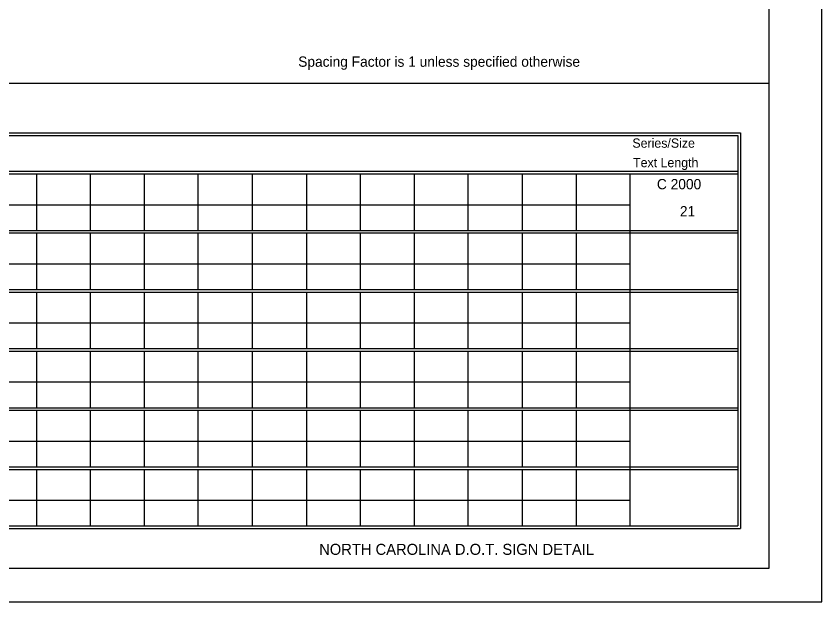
# Model space of a CAD drawing. Extents: x 57.2 to 85.4, y 153.3 to 173.4.
# Drawn here: x 78.56 to 85.38, y 163.43 to 168.39 of the extents above; entities that cross this region are included whole.
import ezdxf

# ---------------------------------------------------------------- set-up
doc = ezdxf.new("R2010")
doc.units = 0
doc.layers.add('Exist Sign D', color=7, linetype='Continuous')
doc.layers.add('Old_Level_2', color=7, linetype='Continuous')

msp = doc.modelspace()

# ---------------------------------------------------------------- linework, layer by layer
at = {"layer": 'Exist Sign D'}
msp.add_lwpolyline([(85.3839, 173.3509), (70.5057, 173.3509), (70.5057, 163.4285), (85.3839, 163.4285)], close=True, dxfattribs=at)
at = {"layer": 'Old_Level_2'}
for p, q in [((76.3534, 167.8204), (84.9353, 167.8204)), ((70.9539, 167.0753), (81.8429, 167.0753)), ((70.9539, 167.0535), (81.8429, 167.0535)), ((78.7311, 167.0535), (78.7311, 166.5748)), ((79.1855, 167.0535), (79.1855, 166.5748)), ((79.6446, 167.0535), (79.6446, 166.5748)), ((80.0991, 167.0535), (80.0991, 166.5748)), ((80.5582, 167.0535), (80.5582, 166.5748)), ((81.0174, 167.0535), (81.0174, 166.5748)), ((81.3556, 167.0753), (84.6717, 167.0753)), ((81.3556, 167.0535), (84.6717, 167.0535)), ((81.4718, 167.0535), (81.4718, 166.5748)), ((81.4718, 167.0535), (81.4718, 166.5748)), ((81.931, 167.0535), (81.931, 166.5748)), ((82.3854, 167.0535), (82.3854, 166.5748)), ((82.8445, 167.0535), (82.8445, 166.5748)), ((83.3037, 167.0535), (83.3037, 166.5748)), ((83.7581, 167.0535), (83.7581, 164.1081)), ((71.413, 166.7924), (81.8429, 166.7924)), ((81.3556, 166.7924), (83.7581, 166.7924)), ((83.7581, 166.6932), (83.7581, 166.5748)), ((70.9539, 166.5748), (81.8429, 166.5748)), ((70.9539, 166.553), (81.8429, 166.553)), ((78.7311, 166.553), (78.7311, 166.0743)), ((79.1855, 166.553), (79.1855, 166.0743)), ((79.6446, 166.553), (79.6446, 166.0743)), ((80.0991, 166.553), (80.0991, 166.0743)), ((80.5582, 166.553), (80.5582, 166.0743)), ((81.0174, 166.553), (81.0174, 166.0743)), ((81.3556, 166.5748), (84.6717, 166.5748)), ((81.3556, 166.553), (84.6717, 166.553)), ((81.4718, 166.553), (81.4718, 166.0743)), ((81.4718, 166.553), (81.4718, 166.0743)), ((81.931, 166.553), (81.931, 166.0743)), ((82.3854, 166.553), (82.3854, 166.0743)), ((82.8445, 166.553), (82.8445, 166.0743)), ((83.3037, 166.553), (83.3037, 166.0743)), ((83.7581, 166.553), (83.7581, 166.3259)), ((71.413, 166.2919), (81.8429, 166.2919)), ((81.3556, 166.2919), (83.7581, 166.2919)), ((83.7581, 166.2301), (83.7581, 166.0743)), ((70.9539, 166.0743), (81.8429, 166.0743)), ((81.3556, 166.0743), (84.6717, 166.0743)), ((70.9539, 166.0526), (81.8429, 166.0526)), ((78.7311, 166.0526), (78.7311, 165.5738)), ((79.1855, 166.0526), (79.1855, 165.5738)), ((79.6446, 166.0526), (79.6446, 165.5738)), ((80.0991, 166.0526), (80.0991, 165.5738)), ((80.5582, 166.0526), (80.5582, 165.5738)), ((81.0174, 166.0526), (81.0174, 165.5738)), ((81.3556, 166.0526), (84.6717, 166.0526)), ((81.4718, 166.0526), (81.4718, 165.5738)), ((81.4718, 166.0526), (81.4718, 165.5738)), ((81.931, 166.0526), (81.931, 165.5738)), ((82.3854, 166.0526), (82.3854, 165.5738)), ((82.8445, 166.0526), (82.8445, 165.5738)), ((83.3037, 166.0526), (83.3037, 165.5738)), ((83.7581, 166.0526), (83.7581, 165.858)), ((71.413, 165.7914), (81.8429, 165.7914)), ((81.3556, 165.7914), (83.7581, 165.7914)), ((83.7581, 165.7148), (83.7581, 165.5738)), ((70.9539, 165.5738), (81.8429, 165.5738)), ((70.9539, 165.5521), (81.8429, 165.5521)), ((78.7311, 165.5521), (78.7311, 165.0733)), ((79.1855, 165.5521), (79.1855, 165.0733)), ((79.6446, 165.5521), (79.6446, 165.0733)), ((80.0991, 165.5521), (80.0991, 165.0733)), ((80.5582, 165.5521), (80.5582, 165.0733)), ((81.0174, 165.5521), (81.0174, 165.0733)), ((81.3556, 165.5738), (84.6717, 165.5738)), ((81.3556, 165.5521), (84.6717, 165.5521)), ((81.4718, 165.5521), (81.4718, 165.0733)), ((81.4718, 165.5521), (81.4718, 165.0733)), ((81.931, 165.5521), (81.931, 165.0733)), ((82.3854, 165.5521), (82.3854, 165.0733)), ((82.8445, 165.5521), (82.8445, 165.0733)), ((83.3037, 165.5521), (83.3037, 165.0733)), ((83.7581, 165.5521), (83.7581, 165.3423)), ((71.413, 165.2909), (81.8429, 165.2909)), ((81.3556, 165.2909), (83.7581, 165.2909)), ((83.7581, 165.1991), (83.7581, 165.0733)), ((78.7311, 165.1291), (78.7311, 165.0733)), ((79.1855, 165.1291), (79.1855, 165.0733)), ((79.6446, 165.1291), (79.6446, 165.0733)), ((80.0991, 165.1291), (80.0991, 165.0733)), ((80.5582, 165.1291), (80.5582, 165.0733)), ((81.0174, 165.1291), (81.0174, 165.0733)), ((81.4718, 165.1291), (81.4718, 165.0733)), ((81.4718, 165.1291), (81.4718, 165.0733)), ((81.931, 165.1291), (81.931, 165.0733)), ((82.3854, 165.1291), (82.3854, 165.0733)), ((82.8445, 165.1291), (82.8445, 165.0733)), ((83.3037, 165.1291), (83.3037, 165.0733)), ((83.7581, 165.1291), (83.7581, 165.0733)), ((70.9539, 165.0733), (81.8429, 165.0733)), ((70.9539, 165.0733), (81.8429, 165.0733)), ((70.9539, 165.0516), (81.8429, 165.0516)), ((70.9539, 165.0516), (81.8429, 165.0516)), ((78.7311, 165.0516), (78.7311, 164.6042)), ((78.7311, 165.0516), (78.7311, 164.5729)), ((79.1855, 165.0516), (79.1855, 164.6042)), ((79.1855, 165.0516), (79.1855, 164.5729)), ((79.6446, 165.0516), (79.6446, 164.6042)), ((79.6446, 165.0516), (79.6446, 164.5729)), ((80.0991, 165.0516), (80.0991, 164.6042)), ((80.0991, 165.0516), (80.0991, 164.5729)), ((80.5582, 165.0516), (80.5582, 164.6042)), ((80.5582, 165.0516), (80.5582, 164.5729)), ((81.0174, 165.0516), (81.0174, 164.6042)), ((81.0174, 165.0516), (81.0174, 164.5729)), ((81.3556, 165.0733), (84.6717, 165.0733)), ((81.3556, 165.0733), (84.6717, 165.0733)), ((81.3556, 165.0516), (84.6717, 165.0516)), ((81.3556, 165.0516), (84.6717, 165.0516)), ((81.4718, 165.0516), (81.4718, 164.6042)), ((81.4718, 165.0516), (81.4718, 164.5729)), ((81.4718, 165.0516), (81.4718, 164.6042)), ((81.4718, 165.0516), (81.4718, 164.5729)), ((81.931, 165.0516), (81.931, 164.6042)), ((81.931, 165.0516), (81.931, 164.5729)), ((82.3854, 165.0516), (82.3854, 164.6042)), ((82.3854, 165.0516), (82.3854, 164.5729)), ((82.8445, 165.0516), (82.8445, 164.6042)), ((82.8445, 165.0516), (82.8445, 164.5729)), ((83.3037, 165.0516), (83.3037, 164.6042)), ((83.3037, 165.0516), (83.3037, 164.5729)), ((83.7581, 165.0516), (83.7581, 164.8362)), ((83.7581, 165.0516), (83.7581, 164.8362)), ((71.413, 164.7905), (81.8429, 164.7905)), ((71.413, 164.7905), (81.8429, 164.7905)), ((81.3556, 164.7905), (83.7581, 164.7905)), ((81.3556, 164.7905), (83.6391, 164.7905)), ((83.7581, 164.7121), (83.7581, 164.6042)), ((83.7581, 164.7121), (83.7581, 164.5729)), ((78.7311, 164.6286), (78.7311, 164.5729)), ((79.1855, 164.6286), (79.1855, 164.5729)), ((79.6446, 164.6286), (79.6446, 164.5729)), ((80.0991, 164.6286), (80.0991, 164.5729)), ((80.5582, 164.6286), (80.5582, 164.5729)), ((81.0174, 164.6286), (81.0174, 164.5729)), ((81.4718, 164.6286), (81.4718, 164.5729)), ((81.4718, 164.6286), (81.4718, 164.5729)), ((81.931, 164.6286), (81.931, 164.5729)), ((82.3854, 164.6286), (82.3854, 164.5729)), ((82.8445, 164.6286), (82.8445, 164.5729)), ((83.3037, 164.6286), (83.3037, 164.5729)), ((83.7581, 164.6286), (83.7581, 164.5729)), ((70.9539, 164.5729), (81.8429, 164.5729)), ((70.9539, 164.5729), (81.8429, 164.5729)), ((81.3556, 164.5729), (84.6717, 164.5729)), ((81.3556, 164.5729), (84.6717, 164.5729)), ((70.9539, 164.5511), (81.8429, 164.5511)), ((70.9539, 164.5511), (81.8429, 164.5511)), ((78.7311, 164.5511), (78.7311, 164.0724)), ((78.7311, 164.5511), (78.7311, 164.0724)), ((79.1855, 164.5511), (79.1855, 164.0724)), ((79.1855, 164.5511), (79.1855, 164.0724)), ((79.6446, 164.5511), (79.6446, 164.0724)), ((79.6446, 164.5511), (79.6446, 164.0724)), ((80.0991, 164.5511), (80.0991, 164.0724)), ((80.0991, 164.5511), (80.0991, 164.0724)), ((80.5582, 164.5511), (80.5582, 164.0724)), ((80.5582, 164.5511), (80.5582, 164.0724)), ((81.0174, 164.5511), (81.0174, 164.0724)), ((81.0174, 164.5511), (81.0174, 164.0724)), ((81.3556, 164.5511), (84.6717, 164.5511)), ((81.3556, 164.5511), (84.6717, 164.5511)), ((81.4718, 164.5511), (81.4718, 164.0724)), ((81.4718, 164.5511), (81.4718, 164.0724)), ((81.4718, 164.5511), (81.4718, 164.0724)), ((81.4718, 164.5511), (81.4718, 164.0724)), ((81.931, 164.5511), (81.931, 164.0724)), ((81.931, 164.5511), (81.931, 164.0724)), ((82.3854, 164.5511), (82.3854, 164.0724)), ((82.3854, 164.5511), (82.3854, 164.0724)), ((82.8445, 164.5511), (82.8445, 164.0724)), ((82.8445, 164.5511), (82.8445, 164.0724)), ((83.3037, 164.5511), (83.3037, 164.0724)), ((83.3037, 164.5511), (83.3037, 164.0724)), ((83.7581, 164.5511), (83.7581, 164.3496)), ((83.7581, 164.5511), (83.7581, 164.3496)), ((71.413, 164.29), (81.8429, 164.29)), ((71.413, 164.29), (81.8429, 164.29)), ((81.3556, 164.29), (83.7581, 164.29)), ((81.3556, 164.29), (83.67, 164.29)), ((83.7581, 164.1968), (83.7581, 164.0724)), ((83.7581, 164.1968), (83.7581, 164.0724)), ((70.9305, 164.0506), (81.8429, 164.0506)), ((70.9539, 164.0724), (81.8429, 164.0724)), ((70.9539, 164.0724), (81.8429, 164.0724)), ((70.9539, 164.0506), (81.8429, 164.0506)), ((81.3556, 164.0724), (84.6717, 164.0724)), ((81.3556, 164.0724), (84.6717, 164.0724)), ((81.3556, 164.0506), (84.6951, 164.0506)), ((81.3556, 164.0506), (84.6717, 164.0506))]:
    msp.add_line(p, q, dxfattribs=at)
msp.add_lwpolyline([(70.7723, 173.0983), (84.9353, 173.0983), (84.9353, 163.7124), (70.7723, 163.7124)], close=True, dxfattribs=at)
for points in [[(70.9305, 164.6042), (70.9305, 167.4017), (81.8429, 167.4017)], [(70.9539, 164.6042), (70.9539, 167.3799), (81.8429, 167.3799)], [(81.3556, 167.4017), (84.6951, 167.4017), (84.6951, 164.6042)], [(81.3556, 167.3799), (84.6717, 167.3799), (84.6717, 164.6042)], [(84.6717, 165.1291), (84.6717, 164.0724)], [(84.6951, 165.1291), (84.6951, 164.0506)]]:
    msp.add_lwpolyline(points, dxfattribs=at)

# ---------------------------------------------------------------- texts
for s, height, p in [('Spacing Factor is 1 unless specified otherwise', 0.08704, (80.9483, 167.9607)), ('Series/Size', 0.078337, (83.7787, 167.275)), ('Text Length', 0.078337, (83.7848, 167.1101)), ('NORTH CAROLINA D.O.T. SIGN DETAIL', 0.093258, (81.1255, 163.8269))]:
    msp.add_text(s, height=height, rotation=360, dxfattribs=at).set_placement(p)
for s, p in [('C 2000', (83.9866, 166.923)), ('21', (84.1811, 166.6932))]:
    msp.add_text(s, height=0.08704, dxfattribs=at).set_placement(p)

doc.saveas('drawing.dxf')
